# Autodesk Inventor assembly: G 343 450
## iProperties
Company: Mayer & Müller AG
Created: 2006-04
Part Number: G 343 450
Document SubType Name: Weldment
Designer: I.Baliuc
Description: Abdeckung, rechts
Material: Geschweißt
Mass: 144.878 g
Surface Area: 148.743 cm^2
Volume: 18.4793 cm^3
Density: 7.84 g/cm^3
Zweck: LBK DC-Schalter
Author: T.Messerschmitt
Revision Number: 343450
